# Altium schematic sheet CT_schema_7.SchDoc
size 218 x 198 mm
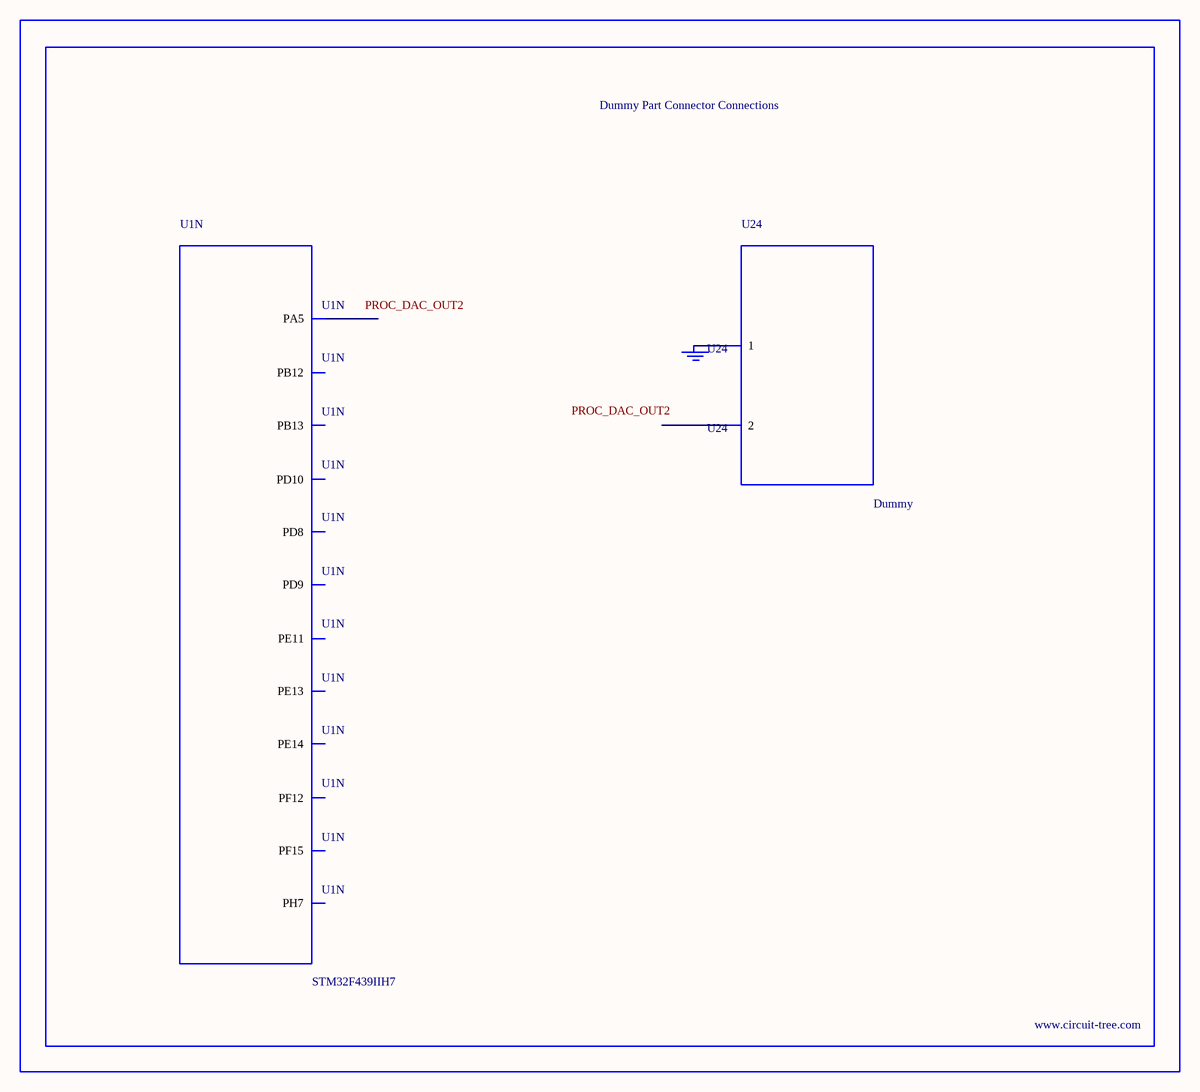
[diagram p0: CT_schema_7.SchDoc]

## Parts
BORDER6  (no value)
GND_INSTANCE_6_0  (no value)
U1  STM32F439IIH7  [UFBGA176_25]  (part N of 14)
U24  Dummy  [DUMMY_PACKAGE_283]

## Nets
NetGND_INSTANCE_6_0_0: GND_INSTANCE_6_0.0(GND) U24.1

Not connected (* = marked no-connect by the designer): U1 N11(PE13) N12(PH7) N15(PD10) P4(PA5) P6(PF12) P7(PF15) P10(PE11) P11(PE14) P12(PB12) P13(PB13) P14(PD9) P15(PD8); U24 2

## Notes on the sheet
- Labels drawn without touching a wire or pin: PROC_DAC_OUT2

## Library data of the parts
BORDER6 = BORDER_PAGE6
GND_INSTANCE_6_0 = GND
